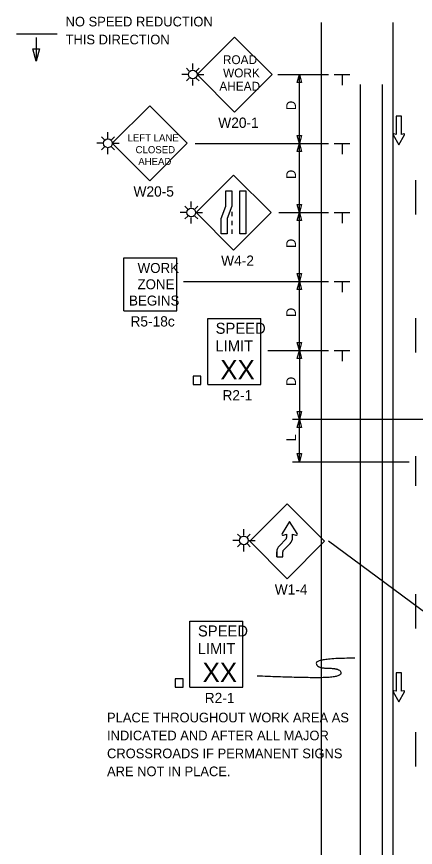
# Model space of a CAD drawing. Extents: x 16473 to 19504, y 4850 to 6923.
# Drawn here: x 16725 to 17013, y 6321 to 6923 of the extents above; entities that cross this region are included whole.
import ezdxf

# ---------------------------------------------------------------- set-up
doc = ezdxf.new("R2010")
doc.units = 0
for name, color, linetype in [('ALI_LEGAL_EX', 7, 'Continuous'), ('MT_SCRATCH_LEVEL_E', 7, 'Continuous'), ('PAVT_EDGE_EX', 7, 'Continuous'), ('TRAFFIC_SIGNS_PR', 7, 'Continuous'), ('TYPICAL_TEXT_DIMEN_PR', 7, 'Continuous')]:
    doc.layers.add(name, color=color, linetype=linetype)

msp = doc.modelspace()

# ---------------------------------------------------------------- linework, layer by layer
at = {"layer": 'ALI_LEGAL_EX'}
for p, q in [((16945.19, 6918.86), (16945.19, 6067.75)), ((16997.19, 6918.86), (16997.19, 6067.75))]:
    msp.add_line(p, q, dxfattribs=at)
for points in [[(17013.43, 6804.69), (17013.43, 6779.69)], [(17013.43, 6704.69), (17013.43, 6679.69)], [(17013.43, 6604.69), (17013.43, 6583.06)], [(17013.43, 6504.69), (17013.43, 6479.69)], [(17013.43, 6404.69), (17013.43, 6379.69)]]:
    msp.add_lwpolyline(points, dxfattribs=at)
at = {"layer": 'MT_SCRATCH_LEVEL_E'}
for p, q in [((17003.35, 6851.09), (16999.61, 6851.09)), ((16999.61, 6851.09), (16999.61, 6837.83)), ((17003.35, 6851.09), (16999.61, 6851.09)), ((16999.61, 6851.09), (16999.61, 6837.83)), ((17003.35, 6837.83), (17003.35, 6851.09)), ((17003.35, 6837.83), (17003.35, 6851.09)), ((16997.35, 6837.46), (17001.5, 6830.22)), ((16997.35, 6837.46), (17001.5, 6830.22)), ((16999.61, 6837.83), (16997.83, 6838.14)), ((16999.61, 6837.83), (16997.83, 6838.14)), ((17001.5, 6830.22), (17005.61, 6837.46)), ((17001.5, 6830.22), (17005.61, 6837.46)), ((17005.13, 6838.14), (17003.35, 6837.83)), ((17005.13, 6838.14), (17003.35, 6837.83)), ((17003.35, 6447.55), (16999.61, 6447.55)), ((16999.61, 6447.55), (16999.61, 6434.29)), ((17003.35, 6447.55), (16999.61, 6447.55)), ((16999.61, 6447.55), (16999.61, 6434.29)), ((17003.35, 6434.29), (17003.35, 6447.55)), ((17003.35, 6434.29), (17003.35, 6447.55)), ((16997.35, 6433.92), (17001.5, 6426.68)), ((16997.35, 6433.92), (17001.5, 6426.68)), ((16999.61, 6434.29), (16997.83, 6434.61)), ((16999.61, 6434.29), (16997.83, 6434.61)), ((17001.5, 6426.68), (17005.61, 6433.92)), ((17001.5, 6426.68), (17005.61, 6433.92)), ((17005.13, 6434.61), (17003.35, 6434.29)), ((17005.13, 6434.61), (17003.35, 6434.29))]:
    msp.add_line(p, q, dxfattribs=at)
for centre, start, end in [((16997.76, 6837.68), 80.03619, 209.77312), ((16997.76, 6837.68), 80.03619, 209.77312), ((17005.2, 6837.68), 330.42484, 99.96381), ((17005.2, 6837.68), 330.42484, 99.96381), ((16997.76, 6434.15), 80.03619, 209.77312), ((16997.76, 6434.15), 80.03619, 209.77312), ((17005.2, 6434.15), 330.42484, 99.96381), ((17005.2, 6434.15), 330.42484, 99.96381)]:
    msp.add_arc(centre, 0.463, start, end, dxfattribs=at)
at = {"layer": 'PAVT_EDGE_EX'}
for p, q in [((16973.43, 6873.99), (16973.43, 6149.2)), ((16989.43, 6873.99), (16989.43, 6149.2))]:
    msp.add_line(p, q, dxfattribs=at)
at = {"layer": 'TRAFFIC_SIGNS_PR'}
for p, q in [((16882.44, 6908.36), (16855.25, 6881.18)), ((16909.63, 6881.18), (16882.44, 6908.36)), ((16852.1, 6884.73), (16852.1, 6889.23)), ((16849.59, 6883.69), (16847.48, 6885.8)), ((16854.61, 6883.69), (16856.72, 6885.8)), ((16848.95, 6881.18), (16844.11, 6881.18)), ((16849.58, 6878.66), (16847.48, 6876.56)), ((16852.1, 6873.21), (16852.1, 6877.62)), ((16854.61, 6878.66), (16856.72, 6876.56)), ((16855.25, 6881.18), (16860.13, 6881.18)), ((16855.25, 6881.18), (16882.44, 6853.99)), ((16882.44, 6853.99), (16909.63, 6881.18)), ((16821, 6858.48), (16793.85, 6831.32)), ((16848.16, 6831.32), (16821, 6858.48)), ((16790.7, 6834.88), (16790.7, 6839.38)), ((16788.18, 6833.84), (16786.08, 6835.94)), ((16793.21, 6833.84), (16795.32, 6835.94)), ((16787.54, 6831.32), (16782.71, 6831.32)), ((16788.18, 6828.81), (16786.08, 6826.7)), ((16790.7, 6823.36), (16790.7, 6827.77)), ((16793.21, 6828.81), (16795.32, 6826.7)), ((16793.85, 6831.32), (16798.73, 6831.32)), ((16793.85, 6831.32), (16821, 6804.17)), ((16821, 6804.17), (16848.16, 6831.32)), ((16881.73, 6808.31), (16854.58, 6781.16)), ((16908.88, 6781.16), (16881.73, 6808.31)), ((16848.57, 6783.66), (16846.46, 6785.77)), ((16851.08, 6784.71), (16851.08, 6789.21)), ((16853.59, 6783.66), (16855.7, 6785.77)), ((16847.93, 6781.15), (16843.09, 6781.15)), ((16854.24, 6781.15), (16859.12, 6781.15)), ((16854.58, 6781.16), (16881.73, 6754.01)), ((16880.48, 6781.65), (16880.48, 6778.45)), ((16881.73, 6754.01), (16908.88, 6781.16)), ((16848.57, 6778.64), (16846.46, 6776.53)), ((16851.08, 6773.19), (16851.08, 6777.6)), ((16853.59, 6778.64), (16855.7, 6776.53)), ((16880.48, 6775.25), (16880.48, 6772.05)), ((16880.48, 6768.85), (16880.48, 6765.65)), ((16802.17, 6710.01), (16802.17, 6748.41)), ((16802.17, 6748.41), (16840.57, 6748.41)), ((16840.57, 6710.01), (16840.57, 6748.41)), ((16802.17, 6710.01), (16840.57, 6710.01)), ((16862.95, 6704.44), (16901.35, 6704.44)), ((16862.95, 6656.44), (16862.95, 6704.44)), ((16901.35, 6656.44), (16901.35, 6704.44)), ((16862.95, 6656.44), (16901.35, 6656.44)), ((16920.52, 6570.06), (16893.37, 6542.91)), ((16947.67, 6542.91), (16920.52, 6570.06)), ((16889.2, 6547.12), (16889.2, 6551.62)), ((16886.69, 6546.08), (16884.58, 6548.19)), ((16891.71, 6546.08), (16893.82, 6548.19)), ((16914.87, 6539.66), (16919.58, 6544.37)), ((16919.58, 6544.37), (16914.87, 6539.66)), ((16886.04, 6543.57), (16881.21, 6543.57)), ((16886.68, 6541.06), (16884.58, 6538.95)), ((16889.2, 6535.6), (16889.2, 6540.01)), ((16891.71, 6541.06), (16893.82, 6538.95)), ((16892.35, 6543.57), (16897.23, 6543.57)), ((16893.37, 6542.91), (16920.52, 6515.76)), ((16917.92, 6536.6), (16922.63, 6541.32)), ((16917.92, 6536.6), (16922.63, 6541.32)), ((16920.52, 6515.76), (16947.67, 6542.91)), ((16913, 6531.54), (16913, 6535.24)), ((16917.32, 6531.54), (16917.32, 6535.24)), ((16913, 6531.54), (16917.32, 6531.54)), ((16850.11, 6485.09), (16888.51, 6485.09)), ((16850.11, 6437.09), (16850.11, 6485.09)), ((16888.51, 6437.09), (16888.51, 6485.09)), ((16850.11, 6437.09), (16888.51, 6437.09))]:
    msp.add_line(p, q, dxfattribs=at)
for points in [[(16880.48, 6796.9), (16880.48, 6785.72), (16877.14, 6776.83), (16877.14, 6765.65), (16872.64, 6765.65), (16872.64, 6776.83), (16875.99, 6785.72), (16875.99, 6796.9)], [(16890.62, 6796.9), (16890.62, 6765.65), (16886.12, 6765.65), (16886.12, 6796.9)], [(16852.34, 6656.44), (16857.94, 6656.44), (16857.94, 6662.61), (16852.34, 6662.61)], [(16839.5, 6437.09), (16845.1, 6437.09), (16845.1, 6443.26), (16839.5, 6443.26)]]:
    msp.add_lwpolyline(points, close=True, dxfattribs=at)
for points in [[(16927.79, 6548.65), (16922.3, 6557.26), (16916.82, 6548.65)], [(16927.79, 6548.65), (16922.3, 6557.26), (16916.82, 6548.65)], [(16917.78, 6547.35), (16920.14, 6548), (16920.14, 6545.7)], [(16917.78, 6547.35), (16918.62, 6547.58), (16920.14, 6548), (16920.14, 6545.7)], [(16924.46, 6545.63), (16924.46, 6548), (16926.82, 6547.35)], [(16913, 6535.24), (16913, 6531.54), (16917.32, 6531.54), (16917.32, 6535.24)]]:
    msp.add_lwpolyline(points, dxfattribs=at)
for centre in [(16852.1, 6881.18), (16790.7, 6831.32), (16851.08, 6781.15), (16889.2, 6543.57)]:
    msp.add_circle(centre, 3.15, dxfattribs=at)
for centre, radius, start, end in [((16917.55, 6548.18), 0.864, 147.52044, 285.3986), ((16917.55, 6548.18), 0.866, 147.52881, 285.38519), ((16918.29, 6545.7), 1.85, 314.21254, 0), ((16918.29, 6545.7), 1.85, 314.2123, 0.1238), ((16918.29, 6545.7), 6.17, 314.21254, 359.38189), ((16918.29, 6545.7), 6.17, 314.76872, 359.37555), ((16927.05, 6548.18), 0.866, 254.67989, 32.28036), ((16919.17, 6535.24), 6.17, 134.21254, 180), ((16919.17, 6535.24), 6.17, 134.21254, 180), ((16919.17, 6535.24), 6.17, 134.21172, 180), ((16919.17, 6535.24), 1.85, 132.37199, 180), ((16919.17, 6535.24), 1.85, 134.21254, 180)]:
    msp.add_arc(centre, radius, start, end, dxfattribs=at)
at = {"layer": 'TYPICAL_TEXT_DIMEN_PR'}
for p, q in [((16724.5, 6910.55), (16753.94, 6910.55)), ((16738.68, 6908.05), (16738.68, 6890.93)), ((16738.68, 6890.93), (16736.32, 6899.72)), ((16736.32, 6899.72), (16738.68, 6899.72)), ((16738.68, 6899.72), (16741.03, 6899.72)), ((16741.03, 6899.72), (16738.68, 6890.93)), ((16913.72, 6881.18), (16950.43, 6881.18)), ((16927.86, 6875.32), (16929.43, 6881.18)), ((16929.43, 6831.18), (16929.43, 6881.18)), ((16929.43, 6881.18), (16931, 6875.32)), ((16954.68, 6881.18), (16965.93, 6881.18)), ((16960.31, 6881.18), (16960.31, 6873.39)), ((16929.43, 6875.32), (16927.86, 6875.32)), ((16931, 6875.32), (16929.43, 6875.32)), ((16929.43, 6831.18), (16927.86, 6837.04)), ((16927.86, 6837.04), (16929.43, 6837.04)), ((16929.43, 6837.04), (16931, 6837.04)), ((16931, 6837.04), (16929.43, 6831.18)), ((16853.97, 6831.18), (16950.43, 6831.18)), ((16924.43, 6831.18), (16950.43, 6831.18)), ((16924.43, 6831.18), (16950.43, 6831.18)), ((16927.86, 6825.32), (16929.43, 6831.18)), ((16929.43, 6831.18), (16931, 6825.32)), ((16929.43, 6781.18), (16929.43, 6831.18)), ((16954.68, 6831.18), (16965.93, 6831.18)), ((16960.31, 6831.18), (16960.31, 6823.39)), ((16929.43, 6825.32), (16927.86, 6825.32)), ((16931, 6825.32), (16929.43, 6825.32)), ((16929.43, 6781.18), (16927.86, 6787.04)), ((16927.86, 6787.04), (16929.43, 6787.04)), ((16929.43, 6787.04), (16931, 6787.04)), ((16931, 6787.04), (16929.43, 6781.18)), ((16914.44, 6781.18), (16950.43, 6781.18)), ((16927.86, 6775.32), (16929.43, 6781.18)), ((16929.43, 6731.7), (16929.43, 6781.7)), ((16929.43, 6781.18), (16931, 6775.32)), ((16954.68, 6781.18), (16965.93, 6781.18)), ((16960.31, 6781.18), (16960.31, 6773.39)), ((16929.43, 6775.32), (16927.86, 6775.32)), ((16931, 6775.32), (16929.43, 6775.32)), ((16929.43, 6731.18), (16927.86, 6737.04)), ((16927.86, 6737.04), (16929.43, 6737.04)), ((16929.43, 6737.04), (16931, 6737.04)), ((16931, 6737.04), (16929.43, 6731.18)), ((16845.33, 6731.18), (16950.43, 6731.18)), ((16927.86, 6725.32), (16929.43, 6731.18)), ((16929.43, 6681.18), (16929.43, 6731.18)), ((16929.43, 6731.18), (16931, 6725.32)), ((16954.68, 6731.18), (16965.93, 6731.18)), ((16960.31, 6731.18), (16960.31, 6723.39)), ((16929.43, 6725.32), (16927.86, 6725.32)), ((16931, 6725.32), (16929.43, 6725.32)), ((16929.43, 6681.18), (16927.86, 6687.04)), ((16927.86, 6687.04), (16929.43, 6687.04)), ((16929.43, 6687.04), (16931, 6687.04)), ((16931, 6687.04), (16929.43, 6681.18)), ((16906.52, 6681.18), (16950.43, 6681.18)), ((16927.86, 6675.32), (16929.43, 6681.18)), ((16929.43, 6681.18), (16929.43, 6631.18)), ((16929.43, 6681.18), (16931, 6675.32)), ((16954.68, 6681.18), (16965.93, 6681.18)), ((16960.31, 6681.18), (16960.31, 6673.39)), ((16929.43, 6675.32), (16927.86, 6675.32)), ((16931, 6675.32), (16929.43, 6675.32)), ((16929.43, 6631.18), (16927.86, 6637.04)), ((16927.86, 6637.04), (16929.43, 6637.04)), ((16929.43, 6637.04), (16931, 6637.04)), ((16931, 6637.04), (16929.43, 6631.18)), ((17034.03, 6631.18), (16924.43, 6631.18)), ((16927.86, 6625.32), (16929.43, 6631.18)), ((16929.43, 6631.18), (16931, 6625.32)), ((16929.43, 6600.35), (16929.43, 6631.18)), ((16929.43, 6625.32), (16927.86, 6625.32)), ((16931, 6625.32), (16929.43, 6625.32)), ((16929.43, 6600.56), (16927.86, 6606.42)), ((16927.86, 6606.42), (16929.43, 6606.42)), ((16929.43, 6606.42), (16931, 6606.42)), ((16931, 6606.42), (16929.43, 6600.56)), ((17009.02, 6600.35), (16924.43, 6600.35)), ((16950.55, 6543.14), (17046.41, 6472.14))]:
    msp.add_line(p, q, dxfattribs=at)
msp.add_open_spline([(16969.46, 6458.16), (16941.61, 6458.16), (16941.61, 6450.92), (16959.5, 6450.92), (16959.5, 6444.05), (16926.57, 6444.05), (16898.7, 6445.22)], degree=2, dxfattribs=at)

# ---------------------------------------------------------------- texts
at = {"layer": 'TRAFFIC_SIGNS_PR'}
for s, height, p in [('ROAD', 6.408, (16873.97, 6888.72)), ('WORK', 6.408, (16874.08, 6879.11)), ('AHEAD', 6.408, (16871.39, 6869.5)), ('W20-1', 7.449, (16870.59, 6842.54)), ('LEFT LANE', 5.2, (16804.88, 6832.72)), ('CLOSED', 5.2, (16810.71, 6824.12)), ('AHEAD', 5.2, (16812.66, 6815.52)), ('W20-5', 7.44, (16809.18, 6792.73)), ('W4-2', 7.44, (16872.69, 6742.57)), ('WORK', 7.217, (16812.17, 6737.38)), ('ZONE', 7.217, (16812.06, 6725.57)), ('BEGINS', 7.217, (16805.98, 6713.76)), ('R5-18c', 7.44, (16806.99, 6698.57)), ('SPEED', 8, (16868.72, 6693.3)), ('LIMIT', 8, (16868.56, 6680.5)), ('XX', 14.031, (16872.07, 6660.2)), ('R2-1', 7.44, (16873.63, 6645)), ('W1-4', 7.44, (16911.53, 6504.32)), ('SPEED', 8, (16855.88, 6473.95)), ('LIMIT', 8, (16855.72, 6461.15)), ('XX', 14.031, (16859.23, 6440.84)), ('R2-1', 7.44, (16860.79, 6425.65)), ('PLACE THROUGHOUT WORK AREA AS', 7, (16790.01, 6411.69)), ('INDICATED AND AFTER ALL MAJOR', 7, (16790.01, 6398.69)), ('CROSSROADS IF PERMANENT SIGNS', 7, (16790.01, 6385.69)), ('ARE NOT IN PLACE.', 7, (16790.01, 6372.69))]:
    msp.add_text(s, height=height, dxfattribs=at).set_placement(p)
at = {"layer": 'TYPICAL_TEXT_DIMEN_PR'}
for s, p in [('NO SPEED REDUCTION', (16760, 6916.04)), ('THIS DIRECTION', (16760, 6903.04))]:
    msp.add_text(s, height=7, dxfattribs=at).set_placement(p)
for s, p in [('D', (16926.87, 6855.4)), ('D', (16926.87, 6805.4)), ('D', (16926.87, 6755.4)), ('D', (16926.87, 6705.4)), ('D', (16926.87, 6655.4)), ('L', (16926.87, 6615.33))]:
    msp.add_text(s, height=7, rotation=90, dxfattribs=at).set_placement(p)

doc.saveas('drawing.dxf')
